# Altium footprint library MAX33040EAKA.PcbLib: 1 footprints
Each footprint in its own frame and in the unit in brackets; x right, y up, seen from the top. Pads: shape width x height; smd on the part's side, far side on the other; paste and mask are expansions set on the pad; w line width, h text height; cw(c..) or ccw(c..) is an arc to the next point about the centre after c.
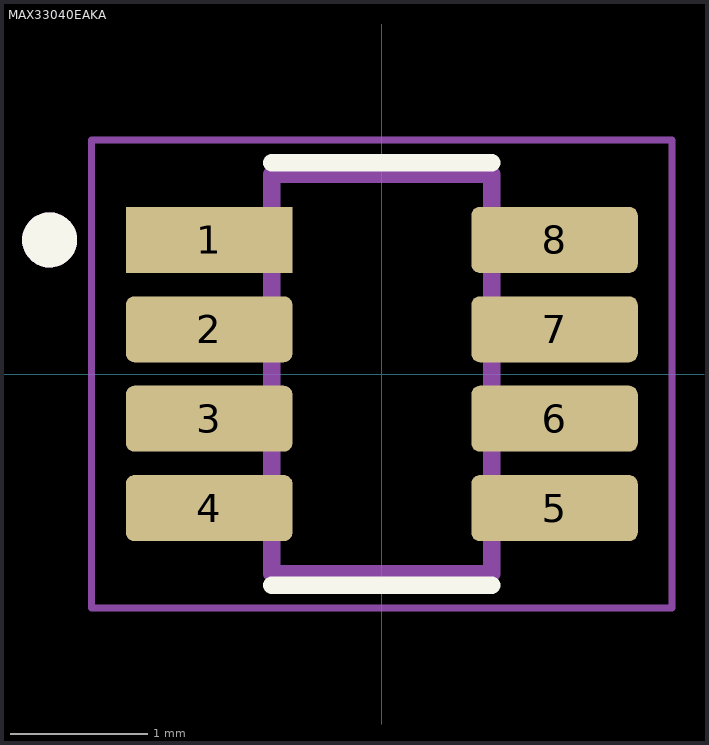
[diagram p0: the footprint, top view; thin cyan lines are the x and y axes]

## MAX33040EAKA [mm]
pads (8):
  rect 1.21x0.48 smd: 1(-1.255,0.975)
  rrect25% 1.21x0.48 smd: 2(-1.255,0.325) 3(-1.255,-0.325) 4(-1.255,-0.975) 5(1.255,-0.975) 6(1.255,-0.325) 7(1.255,0.325) 8(1.255,0.975)
Top Overlay:
  circle w0.2: c-2.415,0.975 r0.1
  lines w0.127: -0.8,-1.535 0.8,-1.535 ; -0.8,1.535 0.8,1.535
Mechanical 13:
  circle w0.2: c-2.415,0.975 r0.1
  lines w0.127: -0.8,-1.45 0.8,-1.45 0.8,1.45 -0.8,1.45 -0.8,-1.45
Mechanical 15:
  lines w0.05: -2.11,-1.7 2.11,-1.7 2.11,1.7 -2.11,1.7 -2.11,-1.7
3D body "MAX33040EAKA.STEP": height 1.45, standoff 0, extent -1.4,-1.447 1.4,1.453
